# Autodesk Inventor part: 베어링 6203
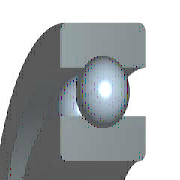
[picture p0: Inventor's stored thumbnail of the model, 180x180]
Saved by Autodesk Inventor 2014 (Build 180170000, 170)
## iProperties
Created: 2012-02
Part Number: 베어링 6203
Material: 강철, 연강
Description: 깊은 그루브 볼 베어링
Document SubType Name: Modeling
Standard: KS B 2023
Designer: mduedu
Standards Organization: KS
Language: ko-KR
Size Designation: 6203 - 17 x 40 x 12
Categories: <MemberInstance><Categories><Category DisplayName="샤프트 부품" InternalName="7f7aeb1f-a693-4053-b835-cee3144e0d98" Mnemonic="SHFT"><Category DisplayName="베어링" Inter
Density: 1 g/cm^3
Appearance: 노란색
IsCustomPart: 1
Author: mduedu
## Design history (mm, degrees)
sketch "스케치" dims "d0" = 5.98 (= -0.26 x WD + 0.26 x BD)
  geometry: L1 (3.01, 14.25)-(8.99, 14.25); L2 (6, 14.25)-(6, 11.26); L3 (6, 14.25)-(6, 17.24); L4 (3.778, 12.249)-(0, 12.249); L5 (0, 8.5)-(12, 8.5); L6 (3.778, 16.251)-(0, 16.251); L7 (0, 20)-(12, 20); L8 (12, 8.5)-(12, 12.249); L9 (8.222, 12.249)-(12, 12.249); L10 (8.222, 16.251)-(12, 16.251); L11 (12, 20)-(12, 16.251); L12 (-1.4, 0)-(8.4, 0) reference; L13 (0, -0.3)-(0, 5.3) reference
  constraints: 22 end point, 4 point on line, 2 collinear, 2 perpendicular, 2 symmetric about line, 1 midpoint, 1 parallel, 14 other
  dimensions: "d9" = 17 diameter of L5 L12 (= WD); "d11" = 40 diameter of L7 L12 (= BD); "d12" = 12 distance between parallel lines of L8 L13 (= KB); "d13" = 24.498 diameter of L9 L12 (= 0.326 x BD + 0.674 x WD)
revolve "본체" stored, may be unused: angle "d6" = 90 deg
revolve "볼" stored, may be unused: angle "d7" = 90 deg
pattern_circular "IDS_ARRAYBALL[SIMPL:T]" dims angle "d3" = 360 deg
body "Solid1"
fillet "모깎기1" dims "d1" = 0.6 (= KRS)
other parameters: "WD" = 17 [user parameter; used in 5 equation terms], "BD" = 40 [user parameter; used in 5 equation terms], "KB" = 12 [user parameter; used in 1 equation term], "KRS" = 0.6 [user parameter; used in 1 equation term], "d4" = 0, "d5" = 0, "d8" = 0, "d14" = 0, "d15" = 0, "BBA" = 0 [user parameter], "BC0" = 4750000 [user parameter], "BC" = 9560000 [user parameter], "WR" = 8.5 (= 0.5 x WD) [user parameter]
